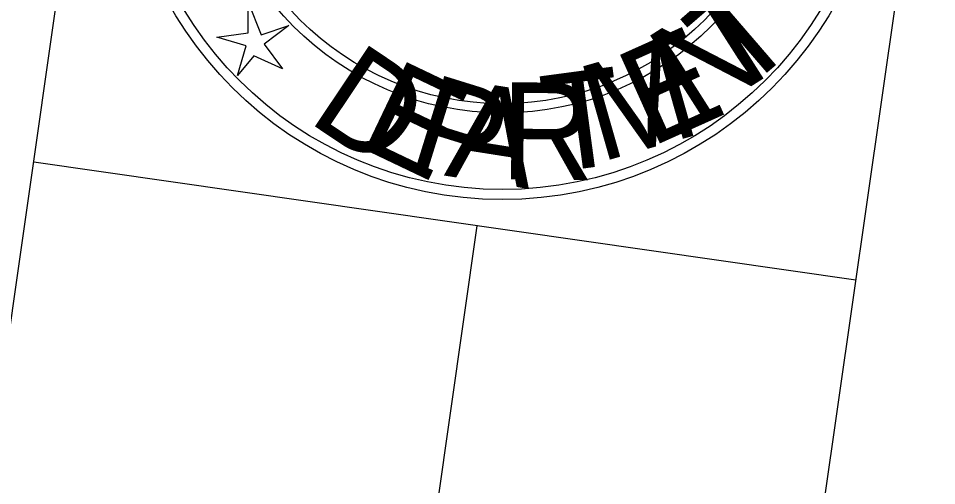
# Model space of a CAD drawing. Extents: x 1797106 to 1798436, y 247408 to 249247.
# Drawn here: x 1798248 to 1798303.3, y 248293.3 to 248321.4 of the extents above; entities that cross this region are included whole.
import ezdxf

# ---------------------------------------------------------------- set-up
doc = ezdxf.new("R2010")
doc.units = 0
for name, color, linetype in [('great seal', 7, 'Continuous'), ('SHT-BDR', 7, 'Continuous'), ('SHT-BNDRY', 7, 'Continuous')]:
    doc.layers.add(name, color=color, linetype=linetype)

msp = doc.modelspace()

# ---------------------------------------------------------------- linework, layer by layer
at = {"layer": 'great seal'}
msp.add_lwpolyline([(1798259.907, 248320.3), (1798261.802, 248320.559), (1798261.803, 248322.417), (1798262.582, 248320.447), (1798264.255, 248321.004), (1798262.768, 248319.89), (1798263.882, 248318.403), (1798262.136, 248319.184), (1798261.169, 248317.996), (1798261.69, 248319.779)], close=True, dxfattribs=at)
msp.add_lwpolyline([(1798259.907, 248320.3), (1798261.802, 248320.559), (1798261.803, 248322.417), (1798262.582, 248320.447), (1798264.255, 248321.004), (1798262.768, 248319.89), (1798263.882, 248318.403), (1798262.136, 248319.184), (1798261.169, 248317.996), (1798261.69, 248319.779)], close=True, dxfattribs=at)
msp.add_lwpolyline([(1798259.907, 248320.3), (1798261.802, 248320.559), (1798261.803, 248322.417), (1798262.582, 248320.447), (1798264.255, 248321.004), (1798262.768, 248319.89), (1798263.882, 248318.403), (1798262.136, 248319.184), (1798261.169, 248317.996), (1798261.69, 248319.779)], close=True, dxfattribs=at)
for radius in [22.994, 22.994, 22.994, 22.389, 22.389, 22.389, 17.779, 17.779, 17.779, 17.222, 17.222, 17.222]:
    msp.add_circle((1798277.117, 248333.513), radius, dxfattribs=at)
at = {"layer": 'SHT-BDR'}
msp.add_lwpolyline([(1798138.486, 247542.494), (1798351.293, 249027.325), (1797410.9, 249162.102), (1797198.094, 247677.271)], close=True, dxfattribs=at)
at = {"layer": 'SHT-BNDRY'}
for p, q in [((1798298.425, 248305.661), (1798248.881, 248312.762)), ((1798165.213, 247538.663), (1798275.608, 248308.931))]:
    msp.add_line(p, q, dxfattribs=at)
msp.add_lwpolyline([(1798179.165, 247473.54), (1798407.932, 249069.733), (1797368.551, 249218.698), (1797139.784, 247622.505)], close=True, dxfattribs=at)

# ---------------------------------------------------------------- texts
at = {"layer": 'great seal'}
for s, rotation, p in [('T', 40.7746, (1798291.529, 248316.83)), ('T', 40.7746, (1798291.529, 248316.83)), ('T', 40.7746, (1798291.529, 248316.83)), ('N', 32.4862, (1798288.629, 248315.122)), ('N', 32.4862, (1798288.629, 248315.122)), ('N', 32.4862, (1798288.629, 248315.122)), ('E', 24.1978, (1798286.027, 248313.636)), ('E', 24.1978, (1798286.027, 248313.636)), ('E', 24.1978, (1798286.027, 248313.636)), ('D', 326.1791, (1798265.293, 248315.281)), ('D', 326.1791, (1798265.293, 248315.281)), ('D', 326.1791, (1798265.293, 248315.281)), ('M', 15.9094, (1798282.98, 248312.746)), ('M', 15.9094, (1798282.98, 248312.746)), ('M', 15.9094, (1798282.98, 248312.746)), ('E', 334.4675, (1798268.265, 248313.793)), ('E', 334.4675, (1798268.265, 248313.793)), ('E', 334.4675, (1798268.265, 248313.793)), ('T', 7.621, (1798279.969, 248312.116)), ('T', 7.621, (1798279.969, 248312.116)), ('T', 7.621, (1798279.969, 248312.116)), ('P', 342.7559, (1798271.274, 248312.566)), ('P', 342.7559, (1798271.274, 248312.566)), ('P', 342.7559, (1798271.274, 248312.566)), ('A', 351.0443, (1798273.578, 248311.97)), ('A', 351.0443, (1798273.578, 248311.97)), ('A', 351.0443, (1798273.578, 248311.97)), ('R', 359.3326, (1798276.996, 248311.745)), ('R', 359.3326, (1798276.996, 248311.745)), ('R', 359.3326, (1798276.996, 248311.745))]:
    msp.add_text(s, height=5.851, rotation=rotation, dxfattribs=at).set_placement(p)

doc.saveas('drawing.dxf')
